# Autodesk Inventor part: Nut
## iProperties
Shininess: 77.0
Length Units: 11269
Angle Units: 11279
Time Units: 11290
Mass Units: 11283
Length Display Precision: 3
Angle Display Precision: 2
Created: 2002-02
Part Number: Nut
Document SubType Name: Modeling
Designer: ***
Density: 1 g/cm^3
Density: 0.0
Volumn: 0.0
Area: 0.0
PropertySet Name: Model Information
Control State: 0
Master: False
Checked Out: False
Author: ***
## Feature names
1. Extrusion1
2. Fillet1
3. Extrusion2
4. Hole1
